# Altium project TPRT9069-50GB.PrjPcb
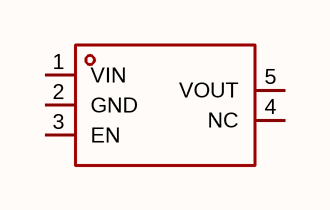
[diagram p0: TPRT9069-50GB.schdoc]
1 sheet, 1 parts. Net scope: global (net labels, ports and power ports of the same name join across sheets).

## Sheet TPRT9069-50GB.schdoc
size 127 x 101 mm

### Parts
U?  tprt9069-50gb  [SOT-23-5_L2.9-W1.7-P0.95-LS2.8-BL]  (value not drawn)

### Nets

Not connected (* = marked no-connect by the designer): U? 1(VIN) 2(GND) 3(EN) 4(NC) 5(VOUT)

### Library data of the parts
U? = tprt9069-50gb: 输出极性:正极;工作电压:36V;输出电压:5V;输出电流:200mA;电源纹波抑制比(PSRR):70dB@(100Hz);输出类型:固定;; Manufacturer: TECH PUBLIC(台舟); AddInBom: yes; ModelId: bc68d73ac92c4e0f9e95c23bce7b0706; ModelTransform: 114.173,110.236,0,0,0,0,0,0,0; Output Configuration: 正极; Voltage - Supply: 36V; Output Voltage: 5V; Output Current: 200mA; Voltage Dropout: 660mV@(100mA); standby current: 2uA; Output Type: 固定; Number of Outputs: 1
